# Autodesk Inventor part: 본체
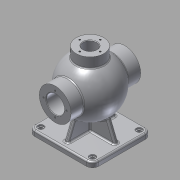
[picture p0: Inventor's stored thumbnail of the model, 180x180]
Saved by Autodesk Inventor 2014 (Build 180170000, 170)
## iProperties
Created: 2015-10
Part Number: 본체
Material: Aluminum 6061
Document SubType Name: Modeling
Designer: youjin08
Density: 2.71 g/cm^3
Appearance: Aluminum - Flat
Mass: 1509.24 g
Surface Area: 1158.1 cm^2
Volume: 556.914 cm^3
Author: youjin08
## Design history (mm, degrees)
sketch "Sketch1"
  geometry: L1 (-62.5, -57.5)-(62.5, -57.5); L2 (62.5, -57.5)-(62.5, 57.5); L3 (62.5, 57.5)-(-62.5, 57.5); L4 (-62.5, 57.5)-(-62.5, -57.5); L5 (-62.5, -57.5)-(62.5, 57.5); L6 (62.5, -57.5)-(-62.5, 57.5); 1 further point
  constraints: 12 end point, 2 midpoint, 2 parallel, 1 horizontal, 1 perpendicular
  dimensions: "d0" = 125 distance of L3.end L2.end; "d1" = 115 distance of L2.end L1.end
extrude "Extrusion1" new body sketch "Sketch1" distance "d2" = 10; taper "d3" = 0 deg
fillet "Fillet1" dims "d4" = 12
sketch "Sketch2"
  geometry: C1 r 6 at (-50.5, 45.5); C2 r 6 at (-50.5, -45.5); C3 r 6 at (50.5, 45.5); C4 r 6 at (50.5, -45.5); A1 r 12 centre (50.5, 45.5) between (62.5, 45.5) and (50.5, 57.5) reference; A2 r 12 centre (-50.5, 45.5) between (-50.5, 57.5) and (-62.5, 45.5) reference; A3 r 12 centre (-50.5, -45.5) between (-62.5, -45.5) and (-50.5, -57.5) reference; A4 r 12 centre (50.5, -45.5) between (50.5, -57.5) and (62.5, -45.5) reference; 1 further point
  constraints: 4 centre point, 4 coincident
  dimensions: "d5" = 12 diameter of C1; "d6" = 12 diameter of C2; "d7" = 12 diameter of C3; "d8" = 12 diameter of C4
extrude "Extrusion2" cut sketch "Sketch2" distance "d9" = 3; taper "d10" = 0 deg
sketch "Sketch3"
  geometry: C1 r 6 at (0, 0) reference; C2 r 6 at (0, 91) reference; C3 r 6 at (101, 91) reference; C4 r 6 at (101, 0) reference; C5 r 4 at (0, 0); C6 r 4 at (0, 91); C7 r 4 at (101, 91); C8 r 4 at (101, 0); 1 further point
  constraints: 4 centre point, 4 coincident
  dimensions: "d11" = 8 diameter of C5; "d12" = 8 diameter of C6; "d13" = 8 diameter of C7; "d14" = 8 diameter of C8
extrude "Extrusion3" cut sketch "Sketch3" stored distance "d15" = 3; taper "d16" = 0 deg
sketch "Sketch4"
  geometry: L1 (50.5, 57.5)-(-50.5, 57.5) reference; L2 (-62.5, 45.5)-(-62.5, -45.5) reference; L3 (-50.5, -57.5)-(50.5, -57.5) reference; L4 (62.5, -45.5)-(62.5, 45.5) reference; C1 r 6 at (50.5, 45.5) reference; C2 r 6 at (-50.5, 45.5) reference; C3 r 6 at (-50.5, -45.5) reference; C4 r 6 at (50.5, -45.5) reference; A1 r 12 centre (50.5, 45.5) between (62.5, 45.5) and (50.5, 57.5) reference; A2 r 12 centre (-50.5, 45.5) between (-50.5, 57.5) and (-62.5, 45.5) reference; A3 r 12 centre (-50.5, -45.5) between (-62.5, -45.5) and (-50.5, -57.5) reference; A4 r 12 centre (50.5, -45.5) between (50.5, -57.5) and (62.5, -45.5) reference; 1 further point
sketch "Sketch5"
  geometry: L1 (0, 32)-(0, 138); A1 r 53 centre (0, 85) between (0, 32) and (0, 138); 1 further point
  constraints: 2 end point, 2 point on circle, 1 centre point, 1 vertical alignment
  dimensions: "d17" = 53 radius of A1; "d18" = 85 distance of point (0, 0) A1.centre
revolve "Revolution1" sketch "Sketch5" stored, may be unused: angle "d19" = 90 deg
sketch "Sketch7"
  geometry: C1 r 53 at (0, 85) reference; C2 r 31 at (0, 85); 1 further point
  constraints: 1 centre point, 1 coincident
  dimensions: "d20" = 62 diameter of C2
extrude "Extrusion4" join sketch "Sketch7" stored distance "d21" = 136; taper "d22" = 0 deg
sketch "Sketch8"
  geometry: L1 (0, 42)-(0, 128); C1 r 53 at (0, 85) reference; A1 r 43 centre (0, 85) between (0, 42) and (0, 128); 1 further point
  constraints: 2 end point, 2 point on circle, 1 centre point, 1 coincident, 1 vertical
  dimensions: "d23" = 43 radius of A1
revolve "Revolution2" sketch "Sketch8" stored, may be unused: angle "d24" = 90 deg
sketch "Sketch9"
  geometry: C1 r 31 at (0, 0) reference; C2 r 17.5 at (0, 0); 1 further point
  constraints: 1 centre point, 1 coincident
  dimensions: "d25" = 35 diameter of C2
extrude "Extrusion5" cut sketch "Sketch9" stored distance "d26" = 136; taper "d27" = 0 deg
workplane "Work Plane1"
sketch "Sketch10"
  geometry: C1 r 27 at (0, 0); 1 further point
  constraints: 1 centre point, 1 coincident
  dimensions: "d29" = 54 diameter of C1
extrude "Extrusion6" join sketch "Sketch10" stored distance "d30" = 136; taper "d31" = 0 deg
sketch "Sketch11"
  geometry: C1 r 27 at (0, 0) reference; C2 r 13 at (0, 0)
  constraints: 1 centre point, 1 coincident
  dimensions: "d32" = 26 diameter of C2
extrude "Extrusion7" cut sketch "Sketch11" stored distance "d33" = 136; taper "d34" = 0 deg
sketch "Sketch13"
  geometry: C1 r 17.5 at (0, 0) reference; C2 r 31 at (0, 0) reference; A1 r 22.5 centre (0, 0) between (0, 22.5) and (-22.5, 0); 3 further points
  constraints: 4 point on circle, 2 horizontal alignment, 2 vertical alignment, 1 centre point, 1 coincident
  dimensions: "d35" = 45 diameter of A1
hole "Hole1" sketch "Sketch13" at (0, 22.5), (-22.5, 0), (0, -22.5), (22.5, 0) diameter "d36" = 3.242; stored, may be unused: countersink angle "d40" = 90 deg, drill point angle "d42" = 118 deg; dims "d37" = 12, "d38" = 4, "d39" = 2, "d41" = 15
sketch "Sketch15"
  geometry: C1 r 17.5 at (0, 0) reference; C2 r 31 at (0, 0) reference; A1 r 24 centre (0, 0) between (0, 24) and (-24, 0); 3 further points
  constraints: 4 point on circle, 2 horizontal alignment, 2 vertical alignment, 1 centre point, 1 coincident
  dimensions: "d43" = 48 diameter of A1
sketch "Sketch16"
  geometry: C1 r 13 at (0, 0) reference; C2 r 27 at (0, 0) reference; A1 r 20 centre (0, 0) between (0, 20) and (20, 0); 2 further points
  constraints: 4 point on circle, 2 horizontal alignment, 2 vertical alignment, 1 centre point, 1 coincident
  dimensions: "d51" = 40 diameter of A1
hole "Hole3" sketch "Sketch16" at (0, 20), (-20, 0), (0, -20), (20, 0) diameter "d52" = 3.242; stored, may be unused: countersink angle "d56" = 90 deg, drill point angle "d58" = 118 deg; dims "d53" = 9, "d54" = 4, "d55" = 2, "d57" = 11
sketch "Sketch17"
  geometry: L1 (-56.5, 10)-(-44.5, 10) reference; L2 (-62.5, 10)-(-50.5, 10) reference; L3 (50.5, 10)-(62.5, 10) reference; L4 (44.5, 10)-(56.5, 10) reference; L5 (-37.379, 47.426)-(-52.5, 10); L6 (37.379, 47.426)-(52.5, 10); L7 (-62.5, 0)-(-62.5, 10) reference; L8 (62.5, 10)-(62.5, 0) reference; A1 r 53 centre (0, 85) between (-27, 130.607) and (27, 130.607) reference; A2 r 53 centre (0, 85) between (-27, 130.607) and (27, 130.607) reference; 1 further point
  constraints: 4 end point, 2 point on circle, 2 point on line
  dimensions: "d59" = 22 deg angle of L7 L5; "d60" = 10 distance from line of L7 L5.end; "d61" = 22 deg angle of L8 L6; "d62" = 10 distance from line of L8 L6.end
sketch "Sketch18"
  geometry: L1 (50.5, 57.5)-(-50.5, 57.5) reference; L2 (-62.5, 45.5)-(-62.5, -45.5) reference; L3 (-50.5, -57.5)-(50.5, -57.5) reference; L4 (62.5, -45.5)-(62.5, 45.5) reference; L5 (-4, -45.5)-(4, -45.5); L6 (4, -45.5)-(4, 45.5); L7 (4, 45.5)-(-4, 45.5); L8 (-4, 45.5)-(-4, -45.5); L9 (-4, -45.5)-(4, 45.5); L10 (4, -45.5)-(-4, 45.5); L11 (-50.5, -4)-(50.5, -4); L12 (50.5, -4)-(50.5, 4); L13 (50.5, 4)-(-50.5, 4); L14 (-50.5, 4)-(-50.5, -4); L15 (-50.5, -4)-(50.5, 4); L16 (50.5, -4)-(-50.5, 4); C1 r 6 at (50.5, -45.5) reference; C2 r 6 at (-50.5, -45.5) reference; C3 r 6 at (-50.5, 45.5) reference; C4 r 6 at (50.5, 45.5) reference; A1 r 12 centre (50.5, 45.5) between (62.5, 45.5) and (50.5, 57.5) reference; A2 r 12 centre (-50.5, 45.5) between (-50.5, 57.5) and (-62.5, 45.5) reference; A3 r 12 centre (-50.5, -45.5) between (-62.5, -45.5) and (-50.5, -57.5) reference; A4 r 12 centre (50.5, -45.5) between (50.5, -57.5) and (62.5, -45.5) reference; 1 further point
  constraints: 24 end point, 4 midpoint, 4 parallel, 2 horizontal, 2 perpendicular
  dimensions: "d63" = 8 distance of L7.end L6.end; "d64" = 91 distance of L6.end L5.end; "d65" = 101 distance of L13.end L12.end; "d66" = 8 distance of L12.end L11.end
fillet "Fillet4" dims "d77" = 3
workplane "Work Plane2"
sketch "Sketch20"
  geometry: C1 r 17.5 at (0, 0) reference; C2 r 18.5 at (0, 0); 1 further point
  constraints: 1 centre point, 1 coincident
  dimensions: "d79" = 37 diameter of C2
sketch "Sketch21"
  geometry: 1 further point
extrude "Extrusion10" join sketch "Sketch20" distance "d80" = 1.75; taper "d81" = 0 deg
sketch "Sketch22"
  geometry: 1 further point
sketch "Sketch23"
  geometry: C1 r 17.5 at (0, 0) reference; C2 r 18.5 at (0, 0); 1 further point
  constraints: 1 centre point, 1 coincident
  dimensions: "d82" = 37 diameter of C2
extrude "Extrusion11" cut sketch "Sketch23" distance "d83" = 1.75; taper "d84" = 0 deg
hole "Hole4" sketch "Sketch15" diameter "d85" = 3.242; stored, may be unused: countersink angle "d89" = 90 deg, drill point angle "d91" = 118 deg; dims "d86" = 16, "d87" = 4, "d88" = 2, "d90" = 19
chamfer "Chamfer1" distance "d92" = 1; stored, may be unused: second distance "d93" = 2, angle "d94" = 45 deg
workplane "Work Plane3"
sketch "Sketch24"
  geometry: 1 further point
sketch "Sketch25"
  geometry: L1 (-27, 150)-(27, 150) reference; L2 (-27, 150)-(-27, 132.286) reference; 2 further points
  constraints: 1 other
  dimensions: "d96" = 10 distance from line of point (0, 140) L1; "d97" = 27 distance from line of L2 point (0, 140)
emboss "Emboss1" sketch "Sketch25" dims "d98" = 0.5, "d99" = 0
fillet "Fillet5" dims "d100" = 3
sketch "Sketch26"
  geometry: L1 (-4, -4)-(4, -4); L2 (4, -4)-(4, 4); L3 (4, 4)-(-4, 4); L4 (-4, 4)-(-4, -4); L5 (-4, -4)-(4, 4); L6 (4, -4)-(-4, 4); 1 further point
  constraints: 12 end point, 2 midpoint, 2 parallel, 1 horizontal, 1 perpendicular
  dimensions: "d101" = 8 distance of L3.end L2.end; "d102" = 8 distance of L2.end L1.end
extrude "Extrusion12" join sketch "Sketch26" stored distance "d103" = 8; taper "d104" = 0 deg
feature "Rib1" dims "d105" = 1, "d106" = 8, "d107" = 0, "d108" = 0, "d109" = 1, "d110" = 1
feature "Rib2" dims "d111" = 1, "d112" = 8, "d113" = 0, "d114" = 0, "d115" = 1, "d116" = 1
sketch "Sketch27"
  geometry: L1 (-57.5, 10)-(-45.5, 10) reference; L2 (45.5, 10)-(57.5, 10) reference; L3 (-47.5, 10)-(-33.719, 44.109); L4 (47.5, 10)-(33.719, 44.109); L5 (-57.5, 0)-(-57.5, 10) reference; L6 (57.5, 10)-(57.5, 0) reference; A1 r 53 centre (0, 85) between (42.113, 117.179) and (42.113, 52.821) reference; 1 further point
  constraints: 4 end point, 2 point on circle, 2 point on line
  dimensions: "d117" = 22 deg angle of L5 L3; "d118" = 10 distance from line of L5 L3.start; "d119" = 22 deg angle of L6 L4; "d120" = 10 distance from line of L6 L4.start
feature "Rib3" dims "d121" = 1, "d122" = 8, "d123" = 0, "d124" = 0, "d125" = 1, "d126" = 1
feature "Rib4" dims "d127" = 1, "d128" = 8, "d129" = 0, "d130" = 0, "d131" = 1, "d132" = 1
fillet "Fillet6" dims "d133" = 3
fillet "Fillet7" dims "d134" = 3
sketch "Sketch28"
  geometry: 1 further point
body "Solid1"
other parameters: "d78" = -16, "d95" = -27.5
